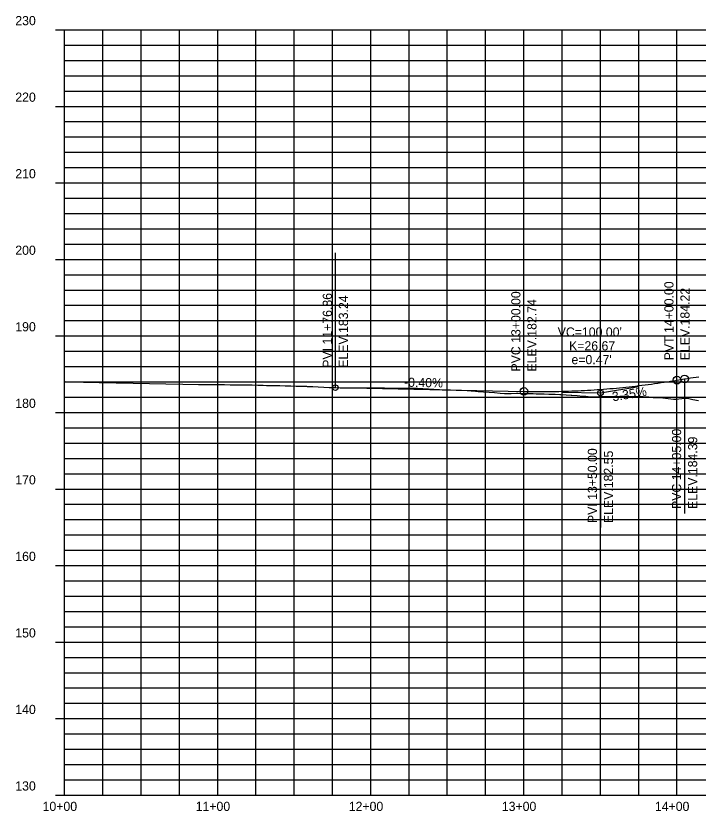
# Model space of a CAD drawing. Extents: x 1409239 to 1412142, y 1838831 to 1842626.
# Drawn here: x 1410813 to 1411258, y 1838831 to 1839350 of the extents above; entities that cross this region are included whole.
import ezdxf

# ---------------------------------------------------------------- set-up
doc = ezdxf.new("R2010")
doc.units = 0
for name, color, linetype in [('63', 7, 'Continuous'), ('R_Axis_Annotation', 7, 'Continuous'), ('R_Exist Surface', 7, 'Continuous'), ('R_Grid', 7, 'Continuous'), ('R_Grid Annot', 7, 'Continuous'), ('R_Grid_Minor', 7, 'Continuous'), ('R_Vert Alg', 7, 'Continuous'), ('R_Vert Alg Annot', 7, 'Continuous')]:
    doc.layers.add(name, color=color, linetype=linetype)

msp = doc.modelspace()

# ---------------------------------------------------------------- linework, layer by layer
at = {"layer": 'R_Exist Surface'}
msp.add_lwpolyline([(1410844.41, 1839111.19), (1410844.67, 1839111.18), (1410856.69, 1839110.93), (1410866.89, 1839110.65), (1410878.01, 1839110.35), (1410889.09, 1839110.11), (1410899.89, 1839109.94), (1410910.48, 1839109.66), (1410921.64, 1839109.48), (1410931.88, 1839109.22), (1410941.73, 1839109.25), (1410942.81, 1839109.25), (1410945.33, 1839109.24), (1410948.92, 1839109.21), (1410952.52, 1839109.17), (1410954.06, 1839109.15), (1410956.12, 1839109.14), (1410959.72, 1839109.1), (1410963.32, 1839109.05), (1410964.66, 1839109.03), (1410966.92, 1839108.98), (1410970.52, 1839108.89), (1410974.12, 1839108.79), (1410976.31, 1839108.72), (1410977.72, 1839108.71), (1410981.31, 1839108.68), (1410984.32, 1839108.64), (1410984.91, 1839108.63), (1410988.51, 1839108.53), (1410992.11, 1839108.43), (1410995.71, 1839108.31), (1410997.47, 1839108.25), (1410999.31, 1839108.2), (1411002.33, 1839108.11), (1411002.91, 1839108.09), (1411006.51, 1839107.93), (1411010.11, 1839107.75), (1411013.7, 1839107.57), (1411017.3, 1839107.37), (1411018.66, 1839107.3), (1411018.9, 1839107.3), (1411020.9, 1839107.25), (1411021.25, 1839107.24), (1411024.5, 1839107.23), (1411028.1, 1839107.21), (1411031.7, 1839107.19), (1411032.97, 1839107.18), (1411035.3, 1839107.16), (1411038.1, 1839107.14), (1411038.9, 1839107.14), (1411042.49, 1839107.11), (1411046.09, 1839107.09), (1411046.76, 1839107.08), (1411049.69, 1839107.06), (1411053.29, 1839107.02), (1411055.91, 1839107), (1411056.89, 1839106.99), (1411060.49, 1839106.96), (1411064.09, 1839106.92), (1411067.69, 1839106.88), (1411069.8, 1839106.86), (1411071.29, 1839106.85), (1411072.84, 1839106.84), (1411074.88, 1839106.81), (1411076.78, 1839106.78), (1411078.48, 1839106.68), (1411082.08, 1839106.46), (1411085.68, 1839106.23), (1411088.13, 1839106.06), (1411089.28, 1839105.99), (1411091.14, 1839105.87), (1411092.88, 1839105.83), (1411096.48, 1839105.74), (1411100.08, 1839105.63), (1411103.68, 1839105.5), (1411107.27, 1839105.35), (1411110.03, 1839105.22), (1411110.87, 1839105.15), (1411114.47, 1839104.81), (1411115.64, 1839104.69), (1411118.07, 1839104.54), (1411121.67, 1839104.29), (1411125.27, 1839104.02), (1411128.87, 1839103.73), (1411131.68, 1839103.49), (1411132.47, 1839103.5), (1411136.07, 1839103.53), (1411139.66, 1839103.54), (1411140.63, 1839103.54), (1411143.26, 1839103.51), (1411146.23, 1839103.45), (1411146.86, 1839103.44), (1411150.46, 1839103.36), (1411152.44, 1839103.3), (1411154.06, 1839103.27), (1411157.66, 1839103.18), (1411160.77, 1839103.08), (1411161.26, 1839103.06), (1411164.86, 1839102.89), (1411167.99, 1839102.72), (1411168.46, 1839102.7), (1411172.05, 1839102.52), (1411175.28, 1839102.34), (1411175.65, 1839102.32), (1411179.25, 1839102.06), (1411182.85, 1839101.78), (1411184.96, 1839101.6), (1411186.45, 1839101.49), (1411189.67, 1839101.23), (1411190.05, 1839101.26), (1411193.46, 1839101.54), (1411193.65, 1839101.54), (1411197.25, 1839101.53), (1411200.84, 1839101.49), (1411202.67, 1839101.45), (1411204.44, 1839101.57), (1411207.05, 1839101.73), (1411208.04, 1839101.7), (1411211.64, 1839101.58), (1411215.24, 1839101.43), (1411215.7, 1839101.41), (1411218.84, 1839101.52), (1411219.96, 1839101.55), (1411222.44, 1839101.4), (1411226.04, 1839101.14), (1411228.84, 1839100.9), (1411229.64, 1839100.91), (1411232.31, 1839100.89), (1411233.23, 1839100.8), (1411236.83, 1839100.39), (1411240.43, 1839099.95), (1411242.16, 1839099.72), (1411244.03, 1839099.82), (1411245.55, 1839099.89), (1411247.63, 1839100.14), (1411250.28, 1839100.42), (1411251.23, 1839100.27), (1411254.83, 1839099.6), (1411258.43, 1839098.85)], dxfattribs=at)
at = {"layer": 'R_Grid'}
for p, q in [((1410844.41, 1838841.03), (1410844.41, 1839341.03)), ((1410844.41, 1839341.03), (1411644.41, 1839341.03)), ((1410844.41, 1839341.03), (1411644.41, 1839341.03)), ((1410944.41, 1838841.03), (1410944.41, 1839341.03)), ((1411044.41, 1838841.03), (1411044.41, 1839341.03)), ((1411144.41, 1838841.03), (1411144.41, 1839341.03)), ((1411244.41, 1838841.03), (1411244.41, 1839341.03)), ((1410844.41, 1839291.03), (1411644.41, 1839291.03)), ((1410844.41, 1839241.03), (1411644.41, 1839241.03)), ((1410844.41, 1839191.03), (1411644.41, 1839191.03)), ((1410844.41, 1839141.03), (1411644.41, 1839141.03)), ((1410844.41, 1839091.03), (1411644.41, 1839091.03)), ((1410844.41, 1839041.03), (1411644.41, 1839041.03)), ((1410844.41, 1838991.03), (1411644.41, 1838991.03)), ((1410844.41, 1838941.03), (1411644.41, 1838941.03)), ((1410844.41, 1838891.03), (1411644.41, 1838891.03)), ((1410844.41, 1838841.03), (1411644.41, 1838841.03))]:
    msp.add_line(p, q, dxfattribs=at)
at = {"layer": 'R_Grid Annot'}
for p, q in [((1410838.41, 1839341.03), (1410844.41, 1839341.03)), ((1410838.41, 1839341.03), (1410844.41, 1839341.03)), ((1410844.41, 1839331.03), (1410847.41, 1839331.03)), ((1410844.41, 1839321.03), (1410847.41, 1839321.03)), ((1410844.41, 1839311.03), (1410847.41, 1839311.03)), ((1410844.41, 1839301.03), (1410847.41, 1839301.03)), ((1410838.41, 1839291.03), (1410844.41, 1839291.03)), ((1410844.41, 1839281.03), (1410847.41, 1839281.03)), ((1410844.41, 1839271.03), (1410847.41, 1839271.03)), ((1410844.41, 1839261.03), (1410847.41, 1839261.03)), ((1410844.41, 1839251.03), (1410847.41, 1839251.03)), ((1410838.41, 1839241.03), (1410844.41, 1839241.03)), ((1410844.41, 1839231.03), (1410847.41, 1839231.03)), ((1410844.41, 1839221.03), (1410847.41, 1839221.03)), ((1410844.41, 1839211.03), (1410847.41, 1839211.03)), ((1410844.41, 1839201.03), (1410847.41, 1839201.03)), ((1410838.41, 1839191.03), (1410844.41, 1839191.03)), ((1410844.41, 1839181.03), (1410847.41, 1839181.03)), ((1410844.41, 1839171.03), (1410847.41, 1839171.03)), ((1410844.41, 1839161.03), (1410847.41, 1839161.03)), ((1410844.41, 1839151.03), (1410847.41, 1839151.03)), ((1410838.41, 1839141.03), (1410844.41, 1839141.03)), ((1410844.41, 1839131.03), (1410847.41, 1839131.03)), ((1410844.41, 1839121.03), (1410847.41, 1839121.03)), ((1410844.41, 1839111.03), (1410847.41, 1839111.03)), ((1410844.41, 1839101.03), (1410847.41, 1839101.03)), ((1410838.41, 1839091.03), (1410844.41, 1839091.03)), ((1410844.41, 1839081.03), (1410847.41, 1839081.03)), ((1410844.41, 1839071.03), (1410847.41, 1839071.03)), ((1410844.41, 1839061.03), (1410847.41, 1839061.03)), ((1410844.41, 1839051.03), (1410847.41, 1839051.03)), ((1410838.41, 1839041.03), (1410844.41, 1839041.03)), ((1410844.41, 1839031.03), (1410847.41, 1839031.03)), ((1410844.41, 1839021.03), (1410847.41, 1839021.03)), ((1410844.41, 1839011.03), (1410847.41, 1839011.03)), ((1410844.41, 1839001.03), (1410847.41, 1839001.03)), ((1410838.41, 1838991.03), (1410844.41, 1838991.03)), ((1410844.41, 1838981.03), (1410847.41, 1838981.03)), ((1410844.41, 1838971.03), (1410847.41, 1838971.03)), ((1410844.41, 1838961.03), (1410847.41, 1838961.03)), ((1410844.41, 1838951.03), (1410847.41, 1838951.03)), ((1410838.41, 1838941.03), (1410844.41, 1838941.03)), ((1410844.41, 1838931.03), (1410847.41, 1838931.03)), ((1410844.41, 1838921.03), (1410847.41, 1838921.03)), ((1410844.41, 1838911.03), (1410847.41, 1838911.03)), ((1410844.41, 1838901.03), (1410847.41, 1838901.03)), ((1410838.41, 1838891.03), (1410844.41, 1838891.03)), ((1410844.41, 1838881.03), (1410847.41, 1838881.03)), ((1410844.41, 1838871.03), (1410847.41, 1838871.03)), ((1410844.41, 1838861.03), (1410847.41, 1838861.03)), ((1410844.41, 1838851.03), (1410847.41, 1838851.03)), ((1410838.41, 1838841.03), (1410844.41, 1838841.03))]:
    msp.add_line(p, q, dxfattribs=at)
at = {"layer": 'R_Grid_Minor'}
for p, q in [((1410869.41, 1838841.03), (1410869.41, 1839341.03)), ((1410894.41, 1838841.03), (1410894.41, 1839341.03)), ((1410919.41, 1838841.03), (1410919.41, 1839341.03)), ((1410969.41, 1838841.03), (1410969.41, 1839341.03)), ((1410994.41, 1838841.03), (1410994.41, 1839341.03)), ((1411019.41, 1838841.03), (1411019.41, 1839341.03)), ((1411069.41, 1838841.03), (1411069.41, 1839341.03)), ((1411094.41, 1838841.03), (1411094.41, 1839341.03)), ((1411119.41, 1838841.03), (1411119.41, 1839341.03)), ((1411169.41, 1838841.03), (1411169.41, 1839341.03)), ((1411194.41, 1838841.03), (1411194.41, 1839341.03)), ((1411219.41, 1838841.03), (1411219.41, 1839341.03)), ((1410844.41, 1839331.03), (1411644.41, 1839331.03)), ((1410844.41, 1839321.03), (1411644.41, 1839321.03)), ((1410844.41, 1839311.03), (1411644.41, 1839311.03)), ((1410844.41, 1839301.03), (1411644.41, 1839301.03)), ((1410844.41, 1839281.03), (1411644.41, 1839281.03)), ((1410844.41, 1839271.03), (1411644.41, 1839271.03)), ((1410844.41, 1839261.03), (1411644.41, 1839261.03)), ((1410844.41, 1839251.03), (1411644.41, 1839251.03)), ((1410844.41, 1839231.03), (1411644.41, 1839231.03)), ((1410844.41, 1839221.03), (1411644.41, 1839221.03)), ((1410844.41, 1839211.03), (1411644.41, 1839211.03)), ((1410844.41, 1839201.03), (1411644.41, 1839201.03)), ((1410844.41, 1839181.03), (1411644.41, 1839181.03)), ((1410844.41, 1839171.03), (1411644.41, 1839171.03)), ((1410844.41, 1839161.03), (1411644.41, 1839161.03)), ((1410844.41, 1839151.03), (1411644.41, 1839151.03)), ((1410844.41, 1839131.03), (1411644.41, 1839131.03)), ((1410844.41, 1839121.03), (1411644.41, 1839121.03)), ((1410844.41, 1839111.03), (1411644.41, 1839111.03)), ((1410844.41, 1839101.03), (1411644.41, 1839101.03)), ((1410844.41, 1839081.03), (1411644.41, 1839081.03)), ((1410844.41, 1839071.03), (1411644.41, 1839071.03)), ((1410844.41, 1839061.03), (1411644.41, 1839061.03)), ((1410844.41, 1839051.03), (1411644.41, 1839051.03)), ((1410844.41, 1839031.03), (1411644.41, 1839031.03)), ((1410844.41, 1839021.03), (1411644.41, 1839021.03)), ((1410844.41, 1839011.03), (1411644.41, 1839011.03)), ((1410844.41, 1839001.03), (1411644.41, 1839001.03)), ((1410844.41, 1838981.03), (1411644.41, 1838981.03)), ((1410844.41, 1838971.03), (1411644.41, 1838971.03)), ((1410844.41, 1838961.03), (1411644.41, 1838961.03)), ((1410844.41, 1838951.03), (1411644.41, 1838951.03)), ((1410844.41, 1838931.03), (1411644.41, 1838931.03)), ((1410844.41, 1838921.03), (1411644.41, 1838921.03)), ((1410844.41, 1838911.03), (1411644.41, 1838911.03)), ((1410844.41, 1838901.03), (1411644.41, 1838901.03)), ((1410844.41, 1838881.03), (1411644.41, 1838881.03)), ((1410844.41, 1838871.03), (1411644.41, 1838871.03)), ((1410844.41, 1838861.03), (1411644.41, 1838861.03)), ((1410844.41, 1838851.03), (1411644.41, 1838851.03))]:
    msp.add_line(p, q, dxfattribs=at)
at = {"layer": 'R_Vert Alg'}
for p, q in [((1411244.41, 1839112.15), (1411249.41, 1839112.99)), ((1411021.27, 1839107.24), (1411144.41, 1839104.78))]:
    msp.add_line(p, q, dxfattribs=at)
for points in [[(1411144.41, 1839104.78), (1411146.5, 1839104.74), (1411148.58, 1839104.71), (1411150.66, 1839104.69), (1411152.75, 1839104.68), (1411154.83, 1839104.67), (1411156.91, 1839104.67), (1411159, 1839104.68), (1411161.08, 1839104.7), (1411163.16, 1839104.73), (1411165.25, 1839104.77), (1411167.33, 1839104.81), (1411169.41, 1839104.86), (1411171.5, 1839104.92), (1411173.58, 1839104.99), (1411175.66, 1839105.07), (1411177.75, 1839105.15), (1411179.83, 1839105.24), (1411181.91, 1839105.35), (1411184, 1839105.45), (1411186.08, 1839105.57), (1411188.16, 1839105.7), (1411190.25, 1839105.83), (1411192.33, 1839105.97), (1411196.5, 1839106.28), (1411198.58, 1839106.44), (1411200.66, 1839106.62), (1411202.75, 1839106.8), (1411204.83, 1839106.99), (1411206.91, 1839107.19), (1411209, 1839107.4), (1411211.08, 1839107.61), (1411213.16, 1839107.83), (1411215.25, 1839108.06), (1411217.33, 1839108.3), (1411219.41, 1839108.55), (1411221.5, 1839108.81), (1411223.58, 1839109.07), (1411225.66, 1839109.34), (1411227.75, 1839109.62), (1411229.83, 1839109.91), (1411231.91, 1839110.2), (1411234, 1839110.51), (1411236.08, 1839110.82), (1411238.16, 1839111.14), (1411240.25, 1839111.47), (1411242.33, 1839111.81), (1411244.41, 1839112.15)], [(1411249.41, 1839112.99), (1411251.29, 1839113.3), (1411253.16, 1839113.59), (1411255.04, 1839113.88), (1411256.91, 1839114.15), (1411258.79, 1839114.41)]]:
    msp.add_lwpolyline(points, dxfattribs=at)
at = {"layer": 'R_Vert Alg Annot'}
for p, q in [((1411021.27, 1839117.24), (1411021.27, 1839195.24)), ((1411244.41, 1839122.15), (1411244.41, 1839200.15)), ((1411144.41, 1839114.78), (1411144.41, 1839192.78)), ((1411021.27, 1839107.24), (1411021.27, 1839117.24)), ((1411244.41, 1839112.15), (1411244.41, 1839122.15)), ((1411144.41, 1839104.78), (1411144.41, 1839114.78)), ((1411249.41, 1839112.99), (1411249.41, 1839102.99)), ((1411194.41, 1839103.78), (1411219.41, 1839107.96)), ((1411169.41, 1839104.28), (1411194.41, 1839103.78)), ((1411194.41, 1839103.78), (1411194.41, 1839093.78)), ((1411249.41, 1839102.99), (1411249.41, 1839024.99)), ((1411194.41, 1839093.78), (1411194.41, 1839015.78))]:
    msp.add_line(p, q, dxfattribs=at)
for centre, radius in [((1411244.41, 1839112.15), 2.5), ((1411249.41, 1839112.99), 2.5), ((1411021.27, 1839107.24), 1.85), ((1411144.41, 1839104.78), 2.5), ((1411194.41, 1839103.78), 1.85)]:
    msp.add_circle(centre, radius, dxfattribs=at)

# ---------------------------------------------------------------- texts
at = {"layer": '63'}
msp.add_text('-', height=0.0001, dxfattribs=at).set_placement((1410844.41, 1838841.03))
at = {"layer": 'R_Axis_Annotation'}
for s, p in [('230', (1410812.17, 1839344.03)), ('230', (1410812.17, 1839344.03)), ('220', (1410812.17, 1839294.03)), ('210', (1410812.17, 1839244.03)), ('200', (1410812.17, 1839194.03)), ('190', (1410812.17, 1839144.03)), ('180', (1410812.17, 1839094.03)), ('170', (1410812.17, 1839044.03)), ('160', (1410812.17, 1838994.03)), ('150', (1410812.17, 1838944.03)), ('140', (1410812.17, 1838894.03)), ('130', (1410812.17, 1838844.03)), ('10+00', (1410830.01, 1838830.68)), ('11+00', (1410930.01, 1838830.68)), ('12+00', (1411030.01, 1838830.68)), ('13+00', (1411130.01, 1838830.68)), ('14+00', (1411230.01, 1838830.68))]:
    msp.add_text(s, height=6, dxfattribs=at).set_placement(p)
at = {"layer": 'R_Vert Alg Annot'}
for s, rotation, p in [('PVT 14+00.00', 90, (1411242.16, 1839125.15)), ('PVC 13+00.00', 90, (1411142.16, 1839117.78)), ('ELEV.184.22', 90, (1411252.66, 1839125.15)), ('PVI 11+76.86', 90, (1411019.02, 1839120.24)), ('ELEV.183.24', 90, (1411029.52, 1839120.24)), ('ELEV.182.74', 90, (1411152.66, 1839117.78)), ('-0.40%', 358.8542, (1411066.08, 1839107.84)), ('3.35%', 9.5088, (1411202.6, 1839098.27)), ('PVC 14+05.00', 90, (1411247.16, 1839027.99)), ('ELEV.184.39', 90, (1411257.66, 1839027.99)), ('PVI 13+50.00', 90, (1411192.16, 1839018.78)), ('ELEV.182.55', 90, (1411202.66, 1839018.78))]:
    msp.add_text(s, height=6, rotation=rotation, dxfattribs=at).set_placement(p)
for s, p in [("VC=100.00'", (1411166.51, 1839140.58)), ('K=26.67', (1411173.94, 1839131.58)), ("e=0.47'", (1411175.51, 1839122.58))]:
    msp.add_text(s, height=6, dxfattribs=at).set_placement(p)

doc.saveas('drawing.dxf')
